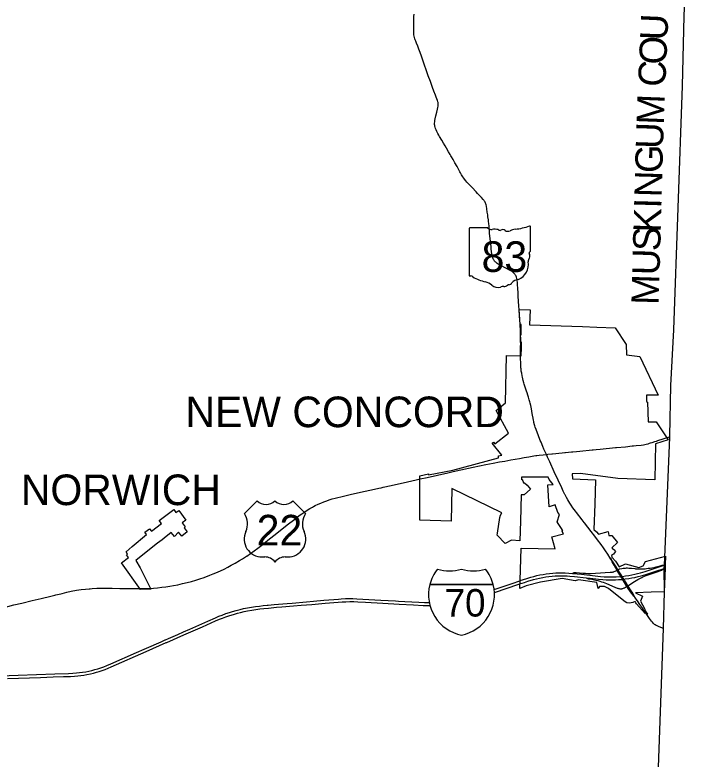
# Model space of a CAD drawing. Extents: x 1913970 to 2287843, y 78841 to 799733.
# Drawn here: x 2176633 to 2201296, y 710619 to 737859 of the extents above; entities that cross this region are included whole.
import ezdxf

# ---------------------------------------------------------------- set-up
doc = ezdxf.new("R2010")
doc.units = 0
for name, color, linetype in [('GM_X_Corporation', 7, 'Continuous'), ('GM_X_Corporation_Text', 7, 'Continuous'), ('GM_X_County', 7, 'Continuous'), ('GM_X_County_Text', 7, 'Continuous'), ('GM_X_Interstate_Location', 7, 'Continuous'), ('GM_X_Interstate_Shield', 7, 'Continuous'), ('GM_X_State_Location', 7, 'Continuous'), ('GM_X_State_Route', 7, 'Continuous'), ('GM_X_State_Shield', 7, 'Continuous'), ('GM_X_US_Location', 7, 'Continuous'), ('GM_X_US_Route', 7, 'Continuous'), ('GM_X_US_Shield', 7, 'Continuous'), ('UT_P_Electric', 7, 'Continuous')]:
    doc.layers.add(name, color=color, linetype=linetype)

msp = doc.modelspace()

# ---------------------------------------------------------------- linework, layer by layer
at = {"layer": 'GM_X_Corporation'}
for points in [[(2191451, 720987), (2191762, 721058), (2191762, 721027), (2192653, 721199), (2194328, 721649), (2194320, 721716), (2194451, 721742), (2194092, 722189), (2194145, 722225), (2194194, 722159), (2194685, 722548), (2194232, 723373), (2194577, 723661), (2194610, 725393), (2195151, 725377), (2195160, 725683), (2195160, 725881), (2195131, 725872), (2195131, 726003), (2195128, 726141), (2195158, 726147), (2195151, 726525), (2195115, 726526), (2195078, 727073), (2195482, 727063), (2195463, 726515), (2197399, 726451), (2197917, 726427), (2198585, 726406), (2198993, 725793), (2199006, 725418), (2199494, 725355), (2200168, 723940), (2199738, 723944), (2199736, 723714), (2199777, 723686), (2199793, 722961), (2200091, 722968), (2200524, 722309), (2200068, 722158), (2200042, 720846), (2198692, 720884), (2197317, 721070), (2197014, 721065), (2197034, 720876), (2197874, 720847), (2197844, 719945), (2197813, 719023), (2197913, 718936), (2197978, 718850), (2198329, 718949), (2198354, 718807), (2198473, 718808), (2198682, 718553), (2198465, 718356), (2198535, 718281), (2198543, 718289), (2198608, 718223), (2198526, 718126), (2198459, 718077), (2198472, 718010), (2198599, 717860), (2198732, 717653), (2198966, 717771), (2199456, 717636), (2199614, 717690), (2199695, 717849), (2200426, 718042), (2200422, 717725), (2200419, 717611), (2200385, 716743), (2199911, 716726), (2199334, 716706), (2199594, 716584), (2199517, 716406), (2199666, 716134), (2199693, 716043), (2199772, 715928), (2199748, 715912), (2199716, 715959), (2199687, 715946), (2199371, 716308), (2199350, 716344), (2199321, 716385), (2199234, 716349), (2199180, 716335), (2199115, 716328), (2199023, 716335), (2198952, 716375), (2198783, 716516), (2198341, 716868), (2198195, 716934), (2198021, 716934), (2197966, 716859), (2197925, 717087), (2197246, 717178), (2197125, 717140), (2196651, 717235), (2195856, 717098), (2195333, 716961), (2195106, 716866), (2195116, 717154), (2195158, 718339), (2196397, 718311), (2196276, 718752), (2196701, 718866), (2196639, 718972), (2196673, 718976), (2196648, 719025), (2196556, 719171), (2196505, 719239), (2196470, 719303), (2196550, 719570), (2196495, 719644), (2196392, 719925), (2196180, 719848), (2196124, 720653), (2196328, 720668), (2196171, 720856), (2196142, 720944), (2195168, 720942), (2195166, 720836), (2195189, 720871), (2195240, 720729), (2195272, 720731), (2195374, 720641), (2195497, 720494), (2195261, 720290), (2195147, 720294), (2195128, 719333), (2195109, 718606), (2194793, 718629), (2194572, 718517), (2194269, 718821), (2194283, 718884), (2194369, 719462), (2194398, 719550), (2194442, 719633), (2192618, 720528), (2192594, 719325), (2191441, 719368)], [(2180536, 717807), (2180787, 718002), (2180715, 718095), (2180755, 718125), (2180698, 718202), (2180922, 718401), (2181445, 718839), (2181383, 718927), (2181552, 719053), (2181630, 718960), (2181998, 719238), (2181914, 719352), (2182449, 719752), (2182522, 719647), (2182625, 719716), (2182890, 719366), (2182751, 719266), (2182859, 719118), (2182821, 719089), (2182936, 718935), (2182740, 718778), (2182622, 718928), (2182467, 718766), (2182355, 718914), (2182098, 718701), (2182018, 718642), (2181854, 718524), (2181374, 718148), (2181054, 717890), (2181214, 717626), (2181601, 716835), (2181232, 716830)]]:
    msp.add_lwpolyline(points, close=True, dxfattribs=at)
at = {"layer": 'GM_X_County'}
msp.add_lwpolyline([(2201296, 742683), (2201102, 737817), (2201047, 735259), (2200727, 726337), (2200609, 724295), (2200576, 722439), (2200575, 722396), (2200380, 717712), (2200376, 717595), (2200385, 716743), (2200352, 715403), (2199774, 699473)], dxfattribs=at)
at = {"layer": 'GM_X_Interstate_Shield'}
for p, q in [((2191808, 717007), (2194131, 717007)), ((2194131, 717007), (2191808, 717007)), ((2194131, 717007), (2191808, 717007))]:
    msp.add_line(p, q, dxfattribs=at)
for centre, start, end in [((2193272, 716637), 141.669, 165.8066), ((2192529, 719016), 253.0091, 286.9909), ((2193411, 719016), 253.0091, 286.9909), ((2192668, 716637), 14.1934, 38.331), ((2193272, 716637), 165.8066, 258.463), ((2192668, 716637), 281.537, 14.1934)]:
    msp.add_arc(centre, 1509, start, end, dxfattribs=at)
at = {"layer": 'GM_X_State_Route'}
msp.add_line((2195135, 725818), (2195136, 725870), dxfattribs=at)
for points in [[(2195030, 727819), (2195029, 727840), (2195023, 727987), (2195021, 728016), (2195018, 728069), (2195011, 728134), (2195006, 728166), (2194995, 728213), (2194980, 728260), (2194968, 728290), (2194954, 728319), (2194937, 728347), (2194918, 728373), (2194897, 728397), (2194873, 728419), (2194836, 728450), (2194795, 728477), (2194725, 728519), (2194619, 728575), (2194595, 728588), (2194406, 728688), (2194335, 728728), (2194279, 728763), (2194252, 728782), (2194226, 728803), (2194202, 728826), (2194180, 728851), (2194170, 728864), (2194151, 728891), (2194142, 728905), (2194126, 728934), (2194113, 728965), (2194103, 728996), (2194094, 729028), (2194087, 729060), (2194078, 729108), (2194076, 729124), (2194069, 729189), (2194057, 729302), (2194049, 729367), (2193998, 729872), (2193990, 729969), (2193977, 730116), (2193966, 730230), (2193961, 730279), (2193952, 730360), (2193937, 730473), (2193933, 730500), (2193928, 730538), (2193914, 730636), (2193896, 730766), (2193880, 730862), (2193869, 730910), (2193860, 730941), (2193849, 730972), (2193835, 731001), (2193819, 731029), (2193802, 731056), (2193782, 731082), (2193762, 731107), (2193696, 731180), (2193561, 731324), (2193506, 731383), (2193359, 731538), (2193302, 731597), (2193169, 731742), (2193126, 731791), (2193084, 731842), (2193054, 731881), (2193017, 731935), (2192974, 732005), (2192933, 732076), (2192909, 732119), (2192869, 732190), (2192806, 732304), (2192726, 732447), (2192661, 732561), (2192604, 732660), (2192579, 732703), (2192555, 732745), (2192498, 732844), (2192417, 732986), (2192368, 733071), (2192310, 733170), (2192252, 733269), (2192169, 733409), (2192144, 733452), (2192104, 733523), (2192065, 733595), (2192037, 733655), (2192018, 733700), (2192002, 733747), (2191994, 733780), (2191989, 733812), (2191987, 733846), (2191988, 733895), (2191992, 733944), (2191998, 733993), (2192011, 734058), (2192036, 734170), (2192067, 734298), (2192094, 734409), (2192109, 734473), (2192117, 734521), (2192121, 734553), (2192122, 734586), (2192120, 734618), (2192115, 734650), (2192107, 734681), (2192091, 734727), (2192043, 734849), (2192014, 734926), (2191961, 735063), (2191943, 735109), (2191920, 735170), (2191882, 735278), (2191832, 735417), (2191755, 735633), (2191716, 735741), (2191678, 735849), (2191619, 736020), (2191582, 736128), (2191517, 736314), (2191489, 736391), (2191434, 736545), (2191412, 736606), (2191372, 736714), (2191329, 736820), (2191297, 736896), (2191279, 736942), (2191264, 736988), (2191250, 737036), (2191239, 737084), (2191231, 737133), (2191225, 737182), (2191223, 737231), (2191222, 737330), (2191224, 737461), (2191224, 737526), (2191224, 737640), (2191226, 737722), (2191229, 737803), (2191235, 737885)], [(2195068, 727239), (2195060, 727350), (2195045, 727595), (2195041, 727660), (2195038, 727709), (2195030, 727819)], [(2195134, 726133), (2195127, 726346), (2195120, 726461), (2195117, 726506), (2195116, 726523), (2195114, 726557), (2195105, 726680), (2195094, 726844), (2195079, 727070), (2195070, 727202), (2195068, 727239)], [(2195136, 725870), (2195136, 726002), (2195134, 726133)], [(2195130, 725391), (2195130, 725423), (2195130, 725480), (2195129, 725545), (2195130, 725593), (2195132, 725691), (2195133, 725723), (2195135, 725818)], [(2195264, 724343), (2195248, 724396), (2195226, 724475), (2195211, 724539), (2195199, 724604), (2195190, 724652), (2195171, 724748), (2195158, 724813), (2195154, 724845), (2195148, 724910), (2195146, 724942), (2195141, 725057), (2195137, 725155), (2195133, 725237), (2195130, 725381), (2195130, 725391)], [(2196079, 721770), (2196065, 721796), (2196021, 721886), (2195985, 721958), (2195940, 722064), (2195878, 722216), (2195853, 722276), (2195773, 722489), (2195712, 722642), (2195695, 722688), (2195667, 722765), (2195651, 722812), (2195649, 722819), (2195637, 722860), (2195619, 722940), (2195610, 722982), (2195602, 723020), (2195577, 723159), (2195572, 723182), (2195570, 723198), (2195556, 723278), (2195543, 723345), (2195541, 723359), (2195526, 723440), (2195503, 723568), (2195485, 723648), (2195472, 723695), (2195450, 723774), (2195421, 723867), (2195396, 723945), (2195370, 724022), (2195348, 724084), (2195321, 724161), (2195295, 724239), (2195264, 724343)], [(2197176, 719642), (2197134, 719697), (2197046, 719816), (2196980, 719910), (2196927, 719993), (2196859, 720105), (2196810, 720191), (2196759, 720288), (2196749, 720307), (2196691, 720425), (2196635, 720543), (2196504, 720827), (2196360, 721140), (2196196, 721498), (2196114, 721677), (2196103, 721703), (2196079, 721770)], [(2198414, 717976), (2198320, 718124), (2198240, 718248), (2198166, 718357), (2198079, 718477), (2197950, 718647), (2197850, 718777), (2197718, 718945), (2197587, 719114), (2197471, 719262), (2197456, 719281), (2197385, 719372), (2197176, 719642)], [(2198916, 717193), (2198907, 717206), (2198845, 717308), (2198832, 717328), (2198763, 717440), (2198703, 717538), (2198694, 717553), (2198630, 717656), (2198535, 717806), (2198493, 717869), (2198461, 717918), (2198454, 717930), (2198439, 717950), (2198414, 717976)], [(2199316, 716541), (2199277, 716585), (2199201, 716675), (2199189, 716692), (2199124, 716781), (2199068, 716863), (2199029, 716924), (2199020, 716938), (2198929, 717087), (2198862, 717201), (2198854, 717215), (2198819, 717271), (2198799, 717304), (2198793, 717313), (2198757, 717368), (2198665, 717519), (2198656, 717534), (2198611, 717609), (2198549, 717712), (2198478, 717837), (2198442, 717909), (2198431, 717933), (2198414, 717976)], [(2199316, 716541), (2199235, 716687), (2199181, 716773), (2199071, 716945), (2199059, 716963), (2199031, 717007), (2198927, 717175), (2198916, 717193)], [(2199598, 716129), (2199492, 716284), (2199403, 716413), (2199395, 716426), (2199316, 716541)], [(2199659, 716040), (2199644, 716063), (2199604, 716120), (2199598, 716129)], [(2199690, 715995), (2199684, 716004), (2199659, 716040)], [(2200354, 715401), (2200265, 715436), (2200173, 715472), (2200129, 715492), (2200086, 715515), (2200058, 715533), (2200032, 715552), (2200007, 715573), (2199984, 715595), (2199951, 715631), (2199920, 715669), (2199881, 715722), (2199851, 715764), (2199749, 715910), (2199717, 715956), (2199690, 715995)]]:
    msp.add_lwpolyline(points, dxfattribs=at)
at = {"layer": 'GM_X_State_Shield'}
for p, q in [((2193927, 730062), (2193271, 730062)), ((2195490, 729214), (2195490, 730104)), ((2193248, 730032), (2193248, 728331)), ((2195490, 729214), (2195490, 729214))]:
    msp.add_line(p, q, dxfattribs=at)
for centre, radius, start, end in [((2193274, 730036), 26, 98.1301, 188.1301), ((2194083, 730259), 252, 231.6195, 271.1119), ((2194691, 732381), 2377, 275.8445, 288.9065), ((2195465, 730108), 25, 351.8621, 97.738), ((2194167, 729107), 904, 80.4867, 94.9883), ((2194372, 730045), 72.7, 219.7921, 297.1024), ((2194479, 729848), 151, 54.4667, 119.1411), ((2194674, 730118), 182, 233.8562, 294.8282), ((2194995, 729542), 478, 97.3462, 120.7689), ((2195579, 728842), 169, 136.8065, 186.9296), ((2195484, 729149), 38.6, 107.944, 210.337), ((2195238, 729036), 232, 340.033, 23.6496), ((2195463, 729211), 26.7, 289.6038, 7.7341), ((2194825, 728728), 595, 292.3089, 8.9858), ((2193274, 728328), 26.2, 171.9584, 258.3066), ((2193278, 728502), 200, 267.339, 280.6039), ((2193319, 728233), 72.1, 29.7484, 93.2717), ((2194229, 729762), 1716, 240.4129, 257.1985), ((2195075, 727854), 326, 94.4031, 142.5768), ((2193718, 727567), 537, 47.1842, 75.836), ((2194298, 728225), 341, 230.7004, 286.2918), ((2194495, 727636), 280, 85.6951, 111.2099), ((2194520, 728097), 182, 268.777, 315.5493), ((2194685, 727933), 51.1, 65.7517, 132.6484), ((2194663, 728166), 192, 282.8732, 323.2771)]:
    msp.add_arc(centre, radius, start, end, dxfattribs=at)
at = {"layer": 'GM_X_US_Route'}
for p, q in [((2200147, 722279), (2200577, 722416)), ((2200047, 722246), (2200097, 722262)), ((2200097, 722262), (2200147, 722279)), ((2197299, 721891), (2197748, 721935)), ((2197748, 721935), (2197781, 721939)), ((2196745, 721836), (2196778, 721839)), ((2189940, 720533), (2190034, 720554)), ((2181499, 716865), (2181561, 716867))]:
    msp.add_line(p, q, dxfattribs=at)
for points in [[(2199226, 722081), (2199261, 722085), (2199357, 722095), (2199537, 722116), (2199622, 722128), (2199724, 722147), (2199780, 722161), (2199794, 722165)], [(2199794, 722165), (2199845, 722180), (2199880, 722191), (2199948, 722212), (2200047, 722246)], [(2197044, 721865), (2197175, 721879), (2197299, 721891)], [(2197781, 721939), (2197893, 721950), (2198047, 721964)], [(2198047, 721964), (2198609, 722019), (2198638, 722021)], [(2198638, 722021), (2198967, 722053), (2199212, 722080), (2199226, 722081)], [(2194778, 721571), (2195091, 721628), (2195264, 721659), (2195433, 721688), (2195615, 721717), (2195689, 721728), (2195721, 721732)], [(2195721, 721732), (2195806, 721742), (2195954, 721758), (2196079, 721770)], [(2196079, 721770), (2196132, 721775), (2196273, 721788), (2196302, 721791)], [(2196302, 721791), (2196653, 721826), (2196745, 721836)], [(2196778, 721839), (2196996, 721861), (2197044, 721865)], [(2192663, 721141), (2192947, 721205), (2193396, 721305), (2193630, 721357), (2193855, 721402), (2193991, 721428), (2194124, 721453), (2194363, 721495)], [(2194363, 721495), (2194558, 721530), (2194778, 721571)], [(2191461, 720873), (2191713, 720930), (2192466, 721097), (2192663, 721141)], [(2190446, 720646), (2190830, 720733), (2191317, 720840), (2191461, 720873)], [(2187560, 719866), (2187618, 719896), (2187721, 719945), (2187825, 719992), (2187931, 720035), (2188038, 720076), (2188130, 720108), (2188244, 720143), (2188351, 720173), (2188452, 720199), (2188554, 720223), (2188892, 720299), (2189165, 720360), (2189901, 720524), (2189940, 720533)], [(2190034, 720554), (2190110, 720571), (2190398, 720635), (2190446, 720646)], [(2185103, 718043), (2185114, 718050), (2185250, 718143), (2185384, 718239), (2185516, 718337), (2185710, 718489), (2185890, 718632), (2186109, 718805), (2186341, 718988), (2186598, 719191), (2186869, 719405), (2187037, 719535), (2187129, 719602), (2187237, 719676), (2187319, 719729), (2187417, 719788), (2187516, 719843), (2187560, 719866)], [(2183828, 717374), (2183881, 717395), (2183988, 717440), (2184153, 717514), (2184287, 717577), (2184419, 717643), (2184550, 717712), (2184694, 717792), (2184851, 717883), (2184963, 717952), (2185103, 718043)], [(2181561, 716867), (2181592, 716868), (2181702, 716877), (2181844, 716891), (2182007, 716909), (2182154, 716928), (2182300, 716950), (2182430, 716972), (2182592, 717003), (2182769, 717042), (2182929, 717080), (2183088, 717123), (2183246, 717169), (2183403, 717219), (2183558, 717272), (2183759, 717347), (2183828, 717374)], [(2178310, 716674), (2178357, 716685), (2178530, 716728), (2178692, 716764), (2178887, 716801), (2179056, 716825), (2179212, 716842), (2179354, 716855)], [(2179354, 716855), (2179382, 716857), (2179464, 716863), (2179628, 716870), (2179775, 716874), (2179907, 716873), (2180187, 716870), (2180467, 716867), (2180747, 716864), (2181086, 716860), (2181192, 716862)], [(2181192, 716862), (2181214, 716862), (2181298, 716861), (2181437, 716862), (2181499, 716865)], [(2176010, 716123), (2176136, 716153), (2176375, 716209), (2176598, 716263), (2176885, 716331), (2177261, 716419), (2177269, 716421)], [(2177269, 716421), (2177593, 716499), (2177947, 716584), (2178089, 716619)], [(2178089, 716619), (2178128, 716628), (2178310, 716674)]]:
    msp.add_lwpolyline(points, dxfattribs=at)
at = {"layer": 'GM_X_US_Shield'}
for p, q in [((2185493, 720073), (2185026, 719606)), ((2187268, 719606), (2186801, 720073)), ((2185680, 718018), (2185774, 718018)), ((2186521, 718018), (2186614, 718018))]:
    msp.add_line(p, q, dxfattribs=at)
for centre, radius, start, end in [((2185820, 720406), 467, 225.573, 314.427), ((2186474, 720406), 467, 225.573, 314.427), ((2184491, 719231), 654, 334.5471, 35.0009), ((2187803, 719231), 654, 144.9991, 205.4529), ((2185673, 718672), 654, 154.8319, 270.6383), ((2186621, 718672), 654, 269.3617, 25.1681), ((2185774, 717551), 467, 36.8699, 90), ((2186521, 717551), 467, 90, 143.1301)]:
    msp.add_arc(centre, radius, start, end, dxfattribs=at)
at = {"layer": 'UT_P_Electric'}
for points in [[(2197035, 717418), (2197044, 717417), (2197354, 717385), (2197859, 717329), (2198055, 717308), (2198186, 717297), (2198301, 717291), (2198416, 717287), (2198514, 717288), (2198629, 717292), (2198760, 717300), (2198799, 717304), (2198845, 717308), (2198859, 717309), (2198973, 717323), (2199086, 717340), (2199199, 717361), (2199312, 717385), (2199408, 717409), (2199518, 717439), (2199691, 717492), (2200351, 717700), (2200381, 717709)], [(2198694, 717553), (2198656, 717534), (2198627, 717516), (2198601, 717500), (2198575, 717486), (2198548, 717473), (2198527, 717465), (2198505, 717458), (2198487, 717454), (2198466, 717450), (2198442, 717447), (2198414, 717444), (2197872, 717413), (2197708, 717404), (2197646, 717404), (2197576, 717405), (2197504, 717409), (2197412, 717414), (2197165, 717434), (2197097, 717437), (2197075, 717433), (2197035, 717418)], [(2200381, 717709), (2200327, 717706), (2200302, 717702), (2200183, 717672), (2200078, 717644), (2200004, 717625), (2199933, 717612), (2199870, 717600), (2199803, 717590), (2199741, 717582), (2199689, 717577), (2199636, 717573), (2199574, 717570), (2199487, 717569), (2199459, 717569), (2199344, 717576), (2199319, 717579), (2199186, 717592), (2199090, 717602), (2199046, 717604), (2198999, 717604), (2198954, 717602), (2198917, 717600), (2198881, 717596), (2198836, 717589), (2198763, 717575), (2198741, 717569), (2198716, 717561), (2198694, 717553)], [(2198784, 717194), (2198831, 717198), (2198862, 717201), (2198907, 717206), (2198961, 717212), (2199091, 717230), (2199204, 717249), (2199316, 717272), (2199427, 717298), (2199538, 717328), (2199711, 717380), (2200117, 717508), (2200344, 717582), (2200377, 717592)], [(2199059, 716963), (2199110, 717000), (2199235, 717079), (2199416, 717191), (2199516, 717247), (2199566, 717272), (2199605, 717290), (2199663, 717314), (2199727, 717339), (2199796, 717365), (2199975, 717425), (2200049, 717453), (2200292, 717541), (2200315, 717550), (2200336, 717560), (2200377, 717592)], [(2194165, 716830), (2194167, 716831), (2194860, 717065), (2195069, 717135), (2195112, 717150), (2195117, 717152), (2195363, 717234), (2195504, 717277), (2195615, 717308), (2195726, 717336), (2195838, 717361), (2195951, 717382), (2196064, 717400), (2196194, 717416), (2196308, 717427), (2196422, 717435), (2196537, 717439), (2196652, 717440), (2196766, 717437), (2196897, 717430), (2197035, 717418)], [(2195133, 717042), (2195183, 717059), (2195272, 717089), (2195396, 717130), (2195605, 717193), (2195716, 717222), (2195828, 717247), (2195941, 717269), (2196055, 717288), (2196168, 717303), (2196283, 717315), (2196397, 717323), (2196512, 717328), (2196627, 717330), (2196742, 717328), (2196840, 717324), (2196938, 717317), (2197101, 717302), (2197533, 717255), (2197672, 717239), (2197981, 717205), (2198144, 717190), (2198259, 717183), (2198373, 717179), (2198488, 717179), (2198602, 717182), (2198717, 717189), (2198784, 717194)], [(2197533, 717255), (2197578, 717229), (2197598, 717223), (2197643, 717217), (2197737, 717202), (2197882, 717170), (2197951, 717152), (2198025, 717133), (2198088, 717113), (2198150, 717092), (2198215, 717069), (2198273, 717045), (2198576, 716916), (2198668, 716880), (2198692, 716872), (2198715, 716865), (2198735, 716861), (2198763, 716857), (2198786, 716855), (2198812, 716856), (2198829, 716857), (2198845, 716860), (2198867, 716865), (2198893, 716873), (2198919, 716884), (2198938, 716893), (2198969, 716910), (2199020, 716938), (2199059, 716963)], [(2194175, 716718), (2195073, 717021), (2195133, 717042)], [(2176096, 713672), (2176752, 713695), (2178096, 713739), (2178588, 713755), (2178752, 713763), (2178883, 713773), (2178997, 713784), (2179111, 713799), (2179225, 713818), (2179337, 713840), (2179450, 713866), (2179561, 713894), (2179671, 713926), (2179781, 713962), (2179889, 714001), (2179996, 714043), (2180147, 714107), (2181077, 714518), (2181364, 714639), (2181620, 714750), (2181815, 714836), (2181980, 714910), (2182129, 714979), (2182145, 714986), (2182248, 715033), (2182593, 715186), (2182803, 715279), (2183028, 715379), (2183358, 715524), (2183688, 715670), (2183973, 715795), (2184094, 715846), (2184216, 715893), (2184355, 715943), (2184479, 715985), (2184589, 716019), (2184731, 716059), (2184874, 716096), (2185001, 716126), (2185146, 716155), (2185291, 716181), (2185437, 716204), (2185583, 716223), (2185714, 716237), (2185855, 716252), (2185893, 716256), (2186122, 716277), (2186596, 716318), (2186775, 716333), (2187298, 716378), (2187560, 716401), (2187936, 716434), (2188295, 716465), (2188475, 716479), (2188573, 716485), (2188721, 716492), (2188868, 716495), (2188999, 716494), (2189147, 716490), (2189360, 716479), (2189802, 716453), (2190015, 716441), (2190555, 716409), (2190670, 716403), (2190899, 716390), (2191407, 716361), (2191620, 716351), (2191751, 716348), (2191790, 716348)], [(2176357, 713572), (2176767, 713586), (2177570, 713612), (2178029, 713627), (2178406, 713640), (2178668, 713649), (2178816, 713657), (2178930, 713667), (2179044, 713680), (2179157, 713696), (2179270, 713715), (2179399, 713741), (2179510, 713768), (2179621, 713797), (2179715, 713826), (2179824, 713862), (2179932, 713900), (2180039, 713942), (2180160, 713993), (2181435, 714557), (2182169, 714882), (2182187, 714890), (2182815, 715166), (2183490, 715465), (2183970, 715677), (2184121, 715740), (2184228, 715782), (2184351, 715828), (2184491, 715875), (2184633, 715918), (2184775, 715958), (2184886, 715988), (2185014, 716017), (2185142, 716044), (2185304, 716074), (2185450, 716097), (2185596, 716116), (2185743, 716131), (2185905, 716147), (2186200, 716175), (2186396, 716191), (2186822, 716224), (2187099, 716248), (2187492, 716282), (2187982, 716326), (2188456, 716366), (2188603, 716376), (2188734, 716381), (2188882, 716384), (2189030, 716382), (2189177, 716377), (2189456, 716362), (2190095, 716326), (2190684, 716292), (2191208, 716262), (2191568, 716242), (2191700, 716238), (2191816, 716237)]]:
    msp.add_lwpolyline(points, dxfattribs=at)

# ---------------------------------------------------------------- texts
at = {"layer": 'GM_X_Corporation_Text'}
for s, p in [('NEW CONCORD', (2182872, 722769)), ('NORWICH', (2176850, 719916))]:
    msp.add_text(s, height=1120, rotation=0, dxfattribs=at).set_placement(p)
at = {"layer": 'GM_X_County_Text'}
for s, rotation, p in [('U', 87.501, (2200497, 736910)), ('O', 87.4982, (2200459, 736026)), ('C', 87.5111, (2200424, 735213)), ('M', 87.8244, (2200369, 733825)), ('U', 88.175, (2200341, 732943)), ('G', 88.3839, (2200316, 732060)), ('N', 88.4037, (2200292, 731176)), ('I', 88.4017, (2200280, 730767)), ('K', 88.4035, (2200256, 729883)), ('S', 88.4017, (2200237, 729205)), ('U', 88.4037, (2200212, 728321)), ('M', 88.4017, (2200182, 727235))]:
    msp.add_text(s, height=1000, rotation=rotation, dxfattribs=at).set_placement(p)
at = {"layer": 'GM_X_Interstate_Location'}
for s in ['.', '-', ',']:
    msp.add_text(s, height=1, dxfattribs=at).set_placement((2197003, 717315))
msp.add_text('70', height=1, rotation=0, dxfattribs=at).set_placement((2196799, 717108))
at = {"layer": 'GM_X_Interstate_Shield'}
msp.add_text('70', height=1006.2, dxfattribs=at).set_placement((2192351, 715837))
at = {"layer": 'GM_X_State_Location'}
msp.add_text('83', height=1, rotation=0, dxfattribs=at).set_placement((2193728, 728693))
for s in ['s', 'r']:
    msp.add_text(s, height=1, dxfattribs=at).set_placement((2193979, 728766))
at = {"layer": 'GM_X_State_Shield'}
msp.add_text('83', height=1120.7, dxfattribs=at).set_placement((2193705, 728451))
at = {"layer": 'GM_X_US_Location'}
for s in ['0', '/']:
    msp.add_text(s, height=1, dxfattribs=at).set_placement((2186005, 718622))
msp.add_text('22', height=1, rotation=0, dxfattribs=at).set_placement((2185799, 718415))
at = {"layer": 'GM_X_US_Shield'}
msp.add_text('22', height=1120.7, dxfattribs=at).set_placement((2185477, 718438))

doc.saveas('drawing.dxf')
